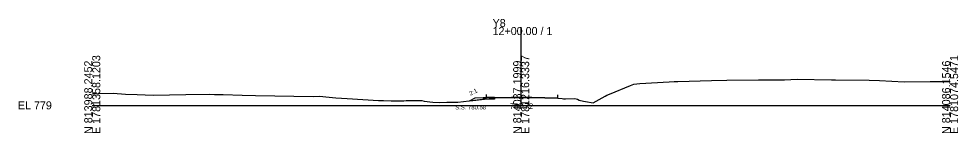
# Model space of a CAD drawing. Extents: x -26 to 303, y -10 to 5036.
# Drawn here: x -25.7 to 302.8, y 3490.3 to 3530.1 of the extents above; entities that cross this region are included whole.
import ezdxf

# ---------------------------------------------------------------- set-up
doc = ezdxf.new("R2010")
doc.units = 0
for name, color, linetype in [('Exist Cross Section Cell', 7, 'Continuous'), ('Exist XS Center Line Elevation Label', 7, 'Continuous'), ('Exist XS Ground Line', 7, 'Continuous'), ('Prop XS Dump Level', 7, 'Continuous'), ('Prop XS Earthwork Shape', 7, 'Continuous'), ('Prop XS EOT Tick Mark', 7, 'Continuous'), ('Prop XS Finish Grade', 7, 'Continuous'), ('Prop XS Finish Grade Earthwork', 7, 'Continuous'), ('Prop XS Finish Grade Pavement', 7, 'Continuous'), ('Prop XS Pvmt Edge Slope', 7, 'Continuous'), ('Prop XS Side Slope Text', 7, 'Continuous'), ('Prop XS SS Elevation Text', 7, 'Continuous'), ('Prop XS Subgrade Earthwork', 7, 'Continuous')]:
    doc.layers.add(name, color=color, linetype=linetype)

msp = doc.modelspace()

# ---------------------------------------------------------------- linework, layer by layer
at = {"layer": 'Exist Cross Section Cell'}
for p, q in [((150, 3500), (150, 3527.3)), ((0, 3500), (150, 3500)), ((150, 3500), (300, 3500))]:
    msp.add_line(p, q, dxfattribs=at)
at = {"layer": 'Exist XS Ground Line'}
for p, q in [((221.93, 3508.73), (233.02, 3508.87)), ((233.02, 3508.87), (242.14, 3508.89)), ((242.14, 3508.89), (246.48, 3509.1)), ((246.48, 3509.1), (258.5, 3508.88)), ((258.5, 3508.88), (259.18, 3508.89)), ((259.18, 3508.89), (259.88, 3508.87)), ((259.88, 3508.87), (271.74, 3508.72)), ((180.89, 3503.92), (188.28, 3506.86)), ((188.28, 3506.86), (189.38, 3507.37)), ((189.38, 3507.37), (191.52, 3507.66)), ((191.52, 3507.66), (201.8, 3508.24)), ((201.8, 3508.24), (203.47, 3508.31)), ((203.47, 3508.31), (203.89, 3508.33)), ((203.89, 3508.33), (204.8, 3508.35)), ((204.8, 3508.35), (216.54, 3508.68)), ((216.54, 3508.68), (221.93, 3508.73)), ((271.74, 3508.72), (275.3, 3508.64)), ((275.3, 3508.64), (283.92, 3508.24)), ((283.92, 3508.24), (293.06, 3508.31)), ((293.06, 3508.31), (295.24, 3508.28)), ((295.24, 3508.28), (296.28, 3508.29)), ((296.28, 3508.29), (300, 3508.3)), ((0, 3503.98), (2.02, 3504.07)), ((2.02, 3504.07), (7.31, 3504.21)), ((7.31, 3504.21), (11.59, 3503.91)), ((11.59, 3503.91), (15.72, 3503.77)), ((15.72, 3503.77), (21.26, 3503.59)), ((21.26, 3503.59), (32.74, 3503.75)), ((32.74, 3503.75), (41.08, 3503.84)), ((41.08, 3503.84), (42.75, 3503.83)), ((42.75, 3503.83), (45.73, 3503.78)), ((45.73, 3503.78), (52.39, 3503.54)), ((52.39, 3503.54), (57.08, 3503.44)), ((57.08, 3503.44), (77.31, 3503.05)), ((77.31, 3503.05), (79.55, 3503.24)), ((79.55, 3503.24), (80.6, 3503.07)), ((80.6, 3503.07), (81.68, 3502.98)), ((81.68, 3502.98), (85.16, 3502.64)), ((85.16, 3502.64), (89.11, 3502.41)), ((89.11, 3502.41), (100.15, 3501.66)), ((131.87, 3501.55), (137.42, 3502.22)), ((137.42, 3502.22), (140.23, 3502.5)), ((140.23, 3502.5), (140.73, 3502.63)), ((140.73, 3502.63), (146.67, 3502.68)), ((146.67, 3502.68), (150, 3502.72)), ((150, 3502.72), (150.64, 3502.73)), ((150.64, 3502.73), (153.69, 3502.68)), ((153.69, 3502.68), (162.8, 3502.5)), ((162.8, 3502.5), (164.34, 3502.35)), ((164.34, 3502.35), (164.79, 3502.3)), ((164.79, 3502.3), (165.22, 3502.28)), ((165.22, 3502.28), (165.55, 3502.26)), ((165.55, 3502.26), (168.77, 3502.34)), ((168.77, 3502.34), (169.72, 3502.17)), ((169.72, 3502.17), (170.31, 3501.79)), ((175.22, 3500.87), (179.4, 3503.25)), ((179.4, 3503.25), (179.9, 3503.5)), ((179.9, 3503.5), (180.89, 3503.92)), ((100.15, 3501.66), (101.84, 3501.66)), ((101.84, 3501.66), (104.57, 3501.62)), ((104.57, 3501.62), (107.45, 3501.62)), ((107.45, 3501.62), (108.31, 3501.62)), ((108.31, 3501.62), (108.92, 3501.62)), ((108.92, 3501.62), (109.8, 3501.63)), ((109.8, 3501.63), (115.21, 3501.68)), ((115.21, 3501.68), (116.03, 3501.46)), ((116.03, 3501.46), (119.05, 3501.09)), ((119.05, 3501.09), (121.46, 3500.99)), ((121.46, 3500.99), (124.02, 3501.06)), ((124.02, 3501.06), (127.82, 3501.06)), ((127.82, 3501.06), (131.87, 3501.55)), ((170.31, 3501.79), (171.85, 3501.4)), ((171.85, 3501.4), (172.47, 3501.3)), ((172.47, 3501.3), (175.22, 3500.87))]:
    msp.add_line(p, q, dxfattribs=at)
at = {"layer": 'Prop XS Earthwork Shape'}
for points in [[(133.84, 3502.45), (132.1, 3501.58), (137.2, 3502.19), (136.74, 3502.65)], [(137.25, 3502.14), (137.2, 3502.19), (137.42, 3502.22), (140.23, 3502.5), (140.73, 3502.63), (140.73, 3502.17)]]:
    msp.add_lwpolyline(points, close=True, dxfattribs=at)
at = {"layer": 'Prop XS EOT Tick Mark'}
for p, q in [((137.84, 3502.73), (137.84, 3503.73)), ((162.8, 3502.62), (162.8, 3503.62))]:
    msp.add_line(p, q, dxfattribs=at)
at = {"layer": 'Prop XS Finish Grade'}
msp.add_line((137.84, 3502.73), (136.74, 3502.65), dxfattribs=at)
at = {"layer": 'Prop XS Finish Grade Earthwork'}
for p, q in [((133.84, 3502.45), (132.1, 3501.58)), ((136.74, 3502.65), (133.84, 3502.45))]:
    msp.add_line(p, q, dxfattribs=at)
at = {"layer": 'Prop XS Finish Grade Pavement'}
for p, q in [((140.73, 3502.75), (137.84, 3502.73)), ((140.73, 3502.75), (146.67, 3502.8)), ((140.73, 3502.75), (140.75, 3502.63)), ((146.67, 3502.8), (150, 3502.85)), ((150, 3502.85), (150.64, 3502.86)), ((150.64, 3502.86), (153.69, 3502.8)), ((153.69, 3502.8), (162.8, 3502.62))]:
    msp.add_line(p, q, dxfattribs=at)
at = {"layer": 'Prop XS Pvmt Edge Slope'}
msp.add_line((137.84, 3502.73), (137.25, 3502.14), dxfattribs=at)
at = {"layer": 'Prop XS Subgrade Earthwork'}
for p, q in [((137.25, 3502.14), (136.74, 3502.65)), ((140.73, 3502.17), (137.25, 3502.14)), ((140.73, 3502.17), (140.73, 3502.63))]:
    msp.add_line(p, q, dxfattribs=at)

# ---------------------------------------------------------------- texts
at = {"layer": 'Exist Cross Section Cell'}
for s, p in [('Y8', (140, 3527.3)), ('12+00.00 / 1', (140, 3524.5)), ('EL 779', (-26, 3498.6))]:
    msp.add_text(s, height=2.8, dxfattribs=at).set_placement(p)
for s, p in [('N 813988.2452', (0, 3490)), ('E 1781358.1203', (2.8, 3490)), ('N 814037.1999', (150, 3490)), ('E 1781216.3337', (152.8, 3490)), ('N 814086.1546', (300, 3490)), ('E 1781074.5471', (302.8, 3490))]:
    msp.add_text(s, height=2.8, rotation=90, dxfattribs=at).set_placement(p)
at = {"layer": 'Exist XS Center Line Elevation Label'}
msp.add_text('781.72', height=2, dxfattribs=at).set_placement((146.03, 3498.72))
at = {"layer": 'Prop XS Dump Level'}
for s, height, p in [('Case1', 0.04, (133.84, 3502.41)), ('Eop', 0.3, (140.73, 3502.33))]:
    msp.add_text(s, height=height, dxfattribs=at).set_placement(p)
at = {"layer": 'Prop XS Side Slope Text'}
msp.add_text('2:1', height=1.5, rotation=26.5651, dxfattribs=at).set_placement((132.3, 3503.36))
at = {"layer": 'Prop XS SS Elevation Text'}
msp.add_text('S.S. 780.58', height=1.5, dxfattribs=at).set_placement((126.92, 3498.58))

doc.saveas('drawing.dxf')
